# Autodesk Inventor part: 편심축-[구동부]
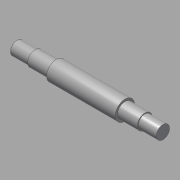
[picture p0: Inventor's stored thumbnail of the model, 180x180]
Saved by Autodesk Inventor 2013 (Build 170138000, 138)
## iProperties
Created: 2015-10
Part Number: 편심축-[구동부]
Document SubType Name: Modeling
Designer: mdu
Density: 7.86 g/cm^3
Material: 강철, 연강
Mass: 1163.82 g
Surface Area: 210.981 cm^2
Volume: 148.069 cm^3
Author: mdu
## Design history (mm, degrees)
sketch "스케치1"
  geometry: L1 (-20.5, -41.331)-(-20.5, 32.669) reference; L2 (7.5, -30.031)-(7.5, 21.369) reference; L3 (135.5, -30.331)-(135.5, 21.669) reference; L4 (121.5, 21.369)-(121.5, -30.031) reference; L5 (184.5, -4.331)-(-7.5, -4.331); L6 (184.5, -4.331)-(184.5, 6.669); L7 (154.5, 8.169)-(121.5, 8.169); L8 (121.5, 8.169)-(121.5, 11.669); L9 (121.5, 11.669)-(7.5, 11.669); L10 (7.5, 11.669)-(7.5, 8.169); L11 (7.5, 8.169)-(-7.5, 8.169); L12 (-7.5, 8.169)-(-7.5, -4.331); L13 (154.5, 8.169)-(154.5, 6.669); L14 (154.5, 6.669)-(184.5, 6.669); C1 r 32.5 at (64.5, -4.331) reference; 1 further point
  constraints: 21 end point, 8 perpendicular, 5 point on line, 1 collinear
  dimensions: "d1" = 25 diameter of L11 L5; "d2" = 32 diameter of L9 L5; "d4" = 15 distance of L10.end L11.end; "d15" = 33 distance of L7.start L7.end; "d26" = 30 distance of L13.end L6.end; "d36" = 22 diameter of L14 L5
revolve "회전1" sketch "스케치1" stored, may be unused: angle "d6" = 90 deg
node "작업 평면1"
sketch "스케치2"
  geometry: C1 r 16 at (0, 0) reference; C2 r 20.75 at (0, 4)
  constraints: 1 centre point, 1 vertical alignment
  dimensions: "d34" = 4 distance of C2.centre C1.centre; "d35" = 41.5 diameter of C2
extrude "돌출1" join sketch "스케치2" stored distance "d9" = 40; taper "d10" = 0 deg
chamfer "모따기1" distance "d11" = 1; stored, may be unused: second distance "d12" = 2, angle "d13" = 45 deg
node "작업 평면2"
sketch "스케치3"
  geometry: L1 (-15, -10)-(-15, 10) reference; L2 (-15, 3)-(0, 3); L3 (0, -3)-(-15, -3); A1 r 3 centre (0, 0) between (0, -3) and (0, 3); 2 further points
  constraints: 4 end point, 2 perpendicular, 2 point on circle, 2 point on line, 2 tangent, 1 centre point, 1 horizontal alignment, 1 midpoint
  dimensions: "d16" = 18 dimension on A1 L1; "d17" = 6 distance between parallel lines of L3 L2
extrude "돌출2" cut sketch "스케치3" distance "d18" = 3.5; taper "d19" = 0 deg
node "솔리드1"
node "참조1"
node "참조2"
node "참조3"
node "참조4"
node "참조5"
other parameters: "d30" = 35
